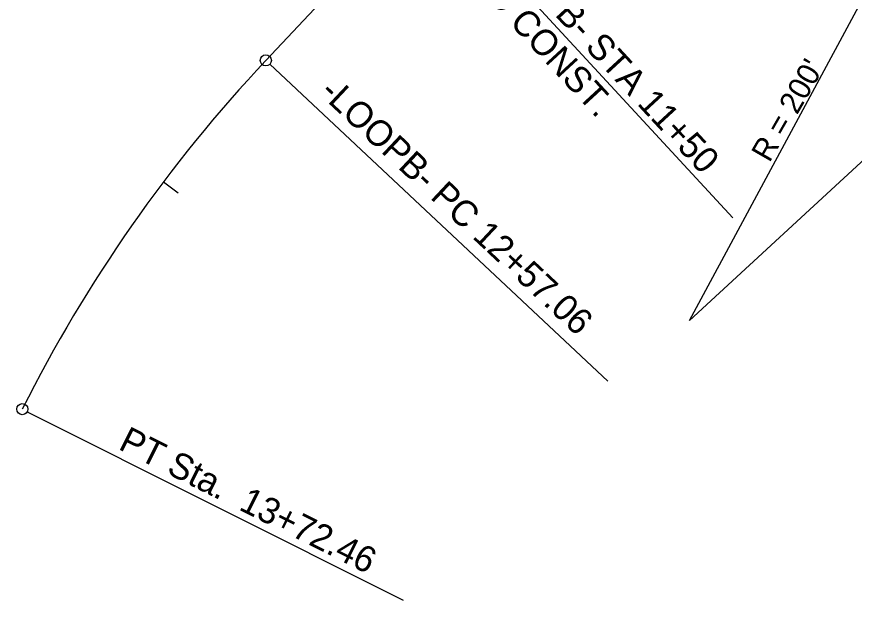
# Model space of a CAD drawing. Extents: x 1702862 to 1704514, y 793768 to 796215.
# Drawn here: x 1703090.2 to 1703316.6, y 794892.5 to 795050.3 of the extents above; entities that cross this region are included whole.
import ezdxf

# ---------------------------------------------------------------- set-up
doc = ezdxf.new("R2010")
doc.units = 0
for name, color, linetype in [('Prop Dimension', 7, 'Continuous'), ('Prop Dimension Text', 7, 'Continuous'), ('Prop DSN Text', 7, 'Continuous'), ('Prop Horizontal Alignment', 7, 'Continuous'), ('Prop Horizontal Alignment Station Label', 7, 'Continuous'), ('Prop Horizontal Alignment Tick Small', 7, 'Continuous'), ('Prop Leader Line Medium', 7, 'Continuous')]:
    doc.layers.add(name, color=color, linetype=linetype)

msp = doc.modelspace()

# ---------------------------------------------------------------- linework, layer by layer
at = {"layer": 'Prop Dimension'}
for q in [(1703366.77, 795144.26), (1703418.98, 795103.79)]:
    msp.add_line((1703272.02, 794968.13), q, dxfattribs=at)
msp.add_arc((1703324.13, 795065.01), 90, 136.7565, 136.7565, dxfattribs=at)
at = {"layer": 'Prop Horizontal Alignment'}
msp.add_line((1703333.42, 795225.96), (1703157.53, 795038.5), dxfattribs=at)
msp.add_arc((1703449.23, 794764.8), 400, 136.823, 153.353, dxfattribs=at)
at = {"layer": 'Prop Horizontal Alignment Station Label'}
for p, q in [((1703158.62, 795037.47), (1703250, 794951.74)), ((1703093.05, 794943.52), (1703194.68, 794892.53))]:
    msp.add_line(p, q, dxfattribs=at)
for centre in [(1703157.53, 795038.5), (1703091.71, 794944.2)]:
    msp.add_circle(centre, 1.5, dxfattribs=at)
at = {"layer": 'Prop Horizontal Alignment Tick Small'}
msp.add_line((1703129.88, 795005.67), (1703133.88, 795002.66), dxfattribs=at)
at = {"layer": 'Prop Leader Line Medium'}
msp.add_line((1703214.05, 795071.43), (1703283.79, 794995.89), dxfattribs=at)

# ---------------------------------------------------------------- texts
at = {"layer": 'Prop Dimension Text'}
msp.add_text("R = 200'", height=6, rotation=60.1006, dxfattribs=at).set_placement((1703293.66, 795010.66))
at = {"layer": 'Prop DSN Text'}
for s, p in [('-LOOPB- STA 11+50', (1703215.71, 795072.18)), ('END CONST.', (1703208, 795065.06))]:
    msp.add_text(s, height=7, rotation=312.7091, dxfattribs=at).set_placement(p)
at = {"layer": 'Prop Horizontal Alignment Station Label'}
for s, rotation, p in [('-LOOPB- PC 12+57.06', 316.823, (1703171.76, 795029.45)), ('PT Sta.  13+72.46', 333.353, (1703117.4, 794933.5))]:
    msp.add_text(s, height=7, rotation=rotation, dxfattribs=at).set_placement(p)

doc.saveas('drawing.dxf')
